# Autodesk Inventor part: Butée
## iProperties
Created: 2007-07
Part Number: Butée
Document SubType Name: Modeling
Designer: EF
Density: 1 g/cm^3
Author: EF
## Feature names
1. Révolution1 [Revolution]
2. Chanfrein1 [Chamfer]
3. Perçage1 [Hole]
